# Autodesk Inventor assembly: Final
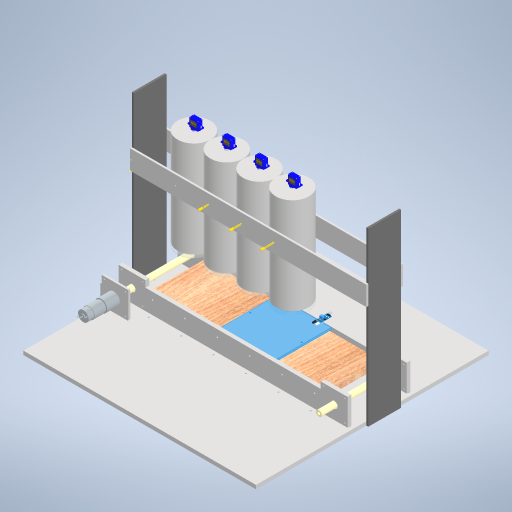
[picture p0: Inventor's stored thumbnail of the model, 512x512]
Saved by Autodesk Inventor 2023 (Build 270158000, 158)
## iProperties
Created: 2022-06
Part Number: Final
Document SubType Name: Assembly
Designer: prana_p9lsmih
Author: prana_p9lsmih
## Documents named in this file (18)
- E:\PRANAV\ENGINEERING EXPLORATION\VIRTUAL IMPLEMENTATION\3D Models\Final.iam
- E:\PRANAV\ENGINEERING EXPLORATION\VIRTUAL IMPLEMENTATION\3D Models\BASE.ipt
- E:\PRANAV\ENGINEERING EXPLORATION\VIRTUAL IMPLEMENTATION\3D Models\conveyor belt sideplank.ipt
- E:\PRANAV\ENGINEERING EXPLORATION\VIRTUAL IMPLEMENTATION\3D Models\Motor clamp p1.ipt
- E:\PRANAV\ENGINEERING EXPLORATION\VIRTUAL IMPLEMENTATION\3D Models\support.ipt
- E:\PRANAV\ENGINEERING EXPLORATION\VIRTUAL IMPLEMENTATION\3D Models\motor.ipt
- E:\PRANAV\ENGINEERING EXPLORATION\VIRTUAL IMPLEMENTATION\3D Models\shaft.ipt
- E:\PRANAV\ENGINEERING EXPLORATION\VIRTUAL IMPLEMENTATION\3D Models\belt support.ipt
- E:\PRANAV\ENGINEERING EXPLORATION\VIRTUAL IMPLEMENTATION\3D Models\support_seed_holder.ipt
- E:\PRANAV\ENGINEERING EXPLORATION\VIRTUAL IMPLEMENTATION\3D Models\side_support_holder.ipt
- E:\PRANAV\ENGINEERING EXPLORATION\VIRTUAL IMPLEMENTATION\3D Models\seed_holder.ipt
- E:\PRANAV\ENGINEERING EXPLORATION\VIRTUAL IMPLEMENTATION\3D Models\seed_disp_lid.ipt
- E:\PRANAV\ENGINEERING EXPLORATION\VIRTUAL IMPLEMENTATION\3D Models\extended_shaft.ipt
- E:\PRANAV\ENGINEERING EXPLORATION\VIRTUAL IMPLEMENTATION\3D Models\lid.ipt
- E:\PRANAV\ENGINEERING EXPLORATION\VIRTUAL IMPLEMENTATION\3D Models\parts\IRsensors.iam
- E:\PRANAV\ENGINEERING EXPLORATION\VIRTUAL IMPLEMENTATION\3D Models\parts\Ensamblaje.iam
- E:\PRANAV\ENGINEERING EXPLORATION\VIRTUAL IMPLEMENTATION\3D Models\pot_mover.ipt
- E:\PRANAV\ENGINEERING EXPLORATION\VIRTUAL IMPLEMENTATION\3D Models\parts\sg90-micro-servo-9g-tower-pro-1.snapshot.3\SG90 - Micro Servo 9g - Tower Pro.iam
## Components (47 placed, 17 different names)
1. BASE:1
2. conveyor belt sideplank:1
3. conveyor belt sideplank:2
4. Motor clamp p1:1 — Mate:7, Mate:8, Mate:9, Mate:10, Mate:20, Mate:21
5. support:1 — Mate:18, Mate:19
6. support:2 — Mate:15, Mate:16, Mate:17
7. support:3 — Mate:11, Mate:12, Mate:13, Mate:14
8. motor:1 — Mate:20, Mate:21, Mate:22
9. shaft:1 — Mate:22, Flush:1
10. shaft:2 — Mate:23, Flush:2
11. belt support:1 — Mate:24, Mate:25, Mate:26
12. support_seed_holder:1
13. side_support_holder:1
14. side_support_holder:2 — Mate:31, Mate:32, Flush:5, Tangent:1, Tangent:2, Tangent:3, Tangent:4
15. seed_holder:1
16. seed_holder:2 — Mate:34, Tangent:2, Flush:7, Flush:8, Mate:40, Mate:41, Mate:48, Mate:50, Mate:71, Mate:75
17. seed_holder:3 — Mate:35, Tangent:3, Flush:8, Flush:9, Mate:42, Mate:43, Mate:47, Mate:53, Mate:72, Mate:76
18. seed_holder:4 — Mate:36, Tangent:4, Flush:9, Mate:44, Mate:45, Mate:46, Mate:52, Mate:73, Mate:88
19. seed_disp_lid:1 — Mate:37, Mate:38, Mate:39, Mate:57
20. seed_disp_lid:2 — Mate:40, Mate:41, Mate:48, Mate:61
21. seed_disp_lid:3 — Mate:42, Mate:43, Mate:47, Mate:65
22. seed_disp_lid:4 — Mate:44, Mate:45, Mate:46, Mate:69
23. extended_shaft:1 — Mate:49, Mate:54, Mate:55, Mate:56, Mate:93
24. extended_shaft:2 — Mate:50, Mate:58, Mate:59, Mate:60, Mate:92
25. extended_shaft:3 — Mate:53, Mate:62, Mate:63, Mate:64, Mate:91
26. extended_shaft:4 — Mate:52, Mate:66, Mate:67, Mate:68, Mate:90
27. seed_disp_lid:5 — Mate:54, Mate:55, Mate:56, Mate:57
28. seed_disp_lid:6 — Mate:58, Mate:59, Mate:60, Mate:61
29. seed_disp_lid:7 — Mate:62, Mate:63, Mate:64, Mate:65
30. seed_disp_lid:8 — Mate:66, Mate:67, Mate:68, Mate:69
31. lid:1 — Mate:70, Mate:74
32. lid:2 — Mate:71, Mate:75
33. lid:3 — Mate:72, Mate:76
34. lid:4 — Mate:73, Mate:88
35. IRsensors:1 [sub-assembly] — Mate:79
36. IRsensors:2 [sub-assembly] — Mate:80
37. IRsensors:3 [sub-assembly] — Mate:81
38. IRsensors:4 [sub-assembly] — Mate:82
39. Ensamblaje:2 [sub-assembly] — Mate:85
40. Ensamblaje:3 [sub-assembly] — Mate:84
41. Ensamblaje:4 [sub-assembly] — Mate:83
42. support_seed_holder:2 — Mate:86, Mate:87, Flush:10
43. pot_mover:1 — Mate:89
44. SG90 - Micro Servo 9g - Tower Pro:1 [sub-assembly] — Mate:93
45. SG90 - Micro Servo 9g - Tower Pro:2 [sub-assembly] — Mate:92
46. SG90 - Micro Servo 9g - Tower Pro:3 [sub-assembly] — Mate:91
47. SG90 - Micro Servo 9g - Tower Pro:4 [sub-assembly] — Mate:90
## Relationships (90: Mate 79, Flush 7, Tangent 4)
- Mate:7: Motor clamp p1:1
- Mate:8: Motor clamp p1:1
- Mate:9: Motor clamp p1:1
- Mate:10: Motor clamp p1:1
- Mate:11: support:3
- Mate:12: support:3
- Mate:13: support:3
- Mate:14: support:3
- Mate:15: support:2
- Mate:16: support:2
- Mate:17: support:2
- Mate:18: support:1
- Mate:19: support:1
- Mate:20: Motor clamp p1:1 ↔ motor:1
- Mate:21: Motor clamp p1:1 ↔ motor:1
- Mate:22: motor:1 ↔ shaft:1
- Flush:1: shaft:1
- Mate:23: shaft:2
- Flush:2: shaft:2
- Mate:24: belt support:1
- Mate:25: belt support:1
- Mate:26: belt support:1
- Mate:31: side_support_holder:2
- Mate:32: side_support_holder:2
- Flush:5: side_support_holder:2
- Tangent:1: side_support_holder:2
- Mate:34: seed_holder:2
- Tangent:2: side_support_holder:2 ↔ seed_holder:2
- Flush:7: seed_holder:2
- Mate:35: seed_holder:3
- Tangent:3: side_support_holder:2 ↔ seed_holder:3
- Flush:8: seed_holder:2 ↔ seed_holder:3
- Mate:36: seed_holder:4
- Tangent:4: side_support_holder:2 ↔ seed_holder:4
- Flush:9: seed_holder:3 ↔ seed_holder:4
- Mate:37: seed_disp_lid:1
- Mate:38: seed_disp_lid:1
- Mate:39: seed_disp_lid:1
- Mate:40: seed_holder:2 ↔ seed_disp_lid:2
- Mate:41: seed_holder:2 ↔ seed_disp_lid:2
- Mate:42: seed_holder:3 ↔ seed_disp_lid:3
- Mate:43: seed_holder:3 ↔ seed_disp_lid:3
- Mate:44: seed_holder:4 ↔ seed_disp_lid:4
- Mate:45: seed_holder:4 ↔ seed_disp_lid:4
- Mate:46: seed_holder:4 ↔ seed_disp_lid:4
- Mate:47: seed_holder:3 ↔ seed_disp_lid:3
- Mate:48: seed_holder:2 ↔ seed_disp_lid:2
- Mate:49: extended_shaft:1
- Mate:50: seed_holder:2 ↔ extended_shaft:2
- Mate:52: seed_holder:4 ↔ extended_shaft:4
- Mate:53: seed_holder:3 ↔ extended_shaft:3
- Mate:54: extended_shaft:1 ↔ seed_disp_lid:5
- Mate:55: extended_shaft:1 ↔ seed_disp_lid:5
- Mate:56: extended_shaft:1 ↔ seed_disp_lid:5
- Mate:57: seed_disp_lid:1 ↔ seed_disp_lid:5
- Mate:58: extended_shaft:2 ↔ seed_disp_lid:6
- Mate:59: extended_shaft:2 ↔ seed_disp_lid:6
- Mate:60: extended_shaft:2 ↔ seed_disp_lid:6
- Mate:61: seed_disp_lid:2 ↔ seed_disp_lid:6
- Mate:62: extended_shaft:3 ↔ seed_disp_lid:7
- Mate:63: extended_shaft:3 ↔ seed_disp_lid:7
- Mate:64: extended_shaft:3 ↔ seed_disp_lid:7
- Mate:65: seed_disp_lid:3 ↔ seed_disp_lid:7
- Mate:66: extended_shaft:4 ↔ seed_disp_lid:8
- Mate:67: extended_shaft:4 ↔ seed_disp_lid:8
- Mate:68: extended_shaft:4 ↔ seed_disp_lid:8
- Mate:69: seed_disp_lid:4 ↔ seed_disp_lid:8
- Mate:70: lid:1
- Mate:71: seed_holder:2 ↔ lid:2
- Mate:72: seed_holder:3 ↔ lid:3
- Mate:73: seed_holder:4 ↔ lid:4
- Mate:74: lid:1
- Mate:75: seed_holder:2 ↔ lid:2
- Mate:76: seed_holder:3 ↔ lid:3
- Mate:79: IRsensors:1
- Mate:80: IRsensors:2
- Mate:81: IRsensors:3
- Mate:82: IRsensors:4
- Mate:83: Ensamblaje:4
- Mate:84: Ensamblaje:3
- Mate:85: Ensamblaje:2
- Mate:86: support_seed_holder:2
- Mate:87: support_seed_holder:2
- Flush:10: support_seed_holder:2
- Mate:88: seed_holder:4 ↔ lid:4
- Mate:89: pot_mover:1
- Mate:90: extended_shaft:4 ↔ SG90 - Micro Servo 9g - Tower Pro:4
- Mate:91: extended_shaft:3 ↔ SG90 - Micro Servo 9g - Tower Pro:3
- Mate:92: extended_shaft:2 ↔ SG90 - Micro Servo 9g - Tower Pro:2
- Mate:93: extended_shaft:1 ↔ SG90 - Micro Servo 9g - Tower Pro:1
